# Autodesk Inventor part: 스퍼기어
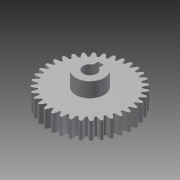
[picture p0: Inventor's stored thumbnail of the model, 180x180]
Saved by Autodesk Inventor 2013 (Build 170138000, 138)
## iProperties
Created: 2013-08
Part Number: 스퍼기어
Material: 강
Document SubType Name: Modeling
Designer: 한국산업디자인학원
Categories: <?xml version="1.0" encoding="UTF-16"?> <MemberInstance><Categories><FamilyTemplate><FamilyTemplateParameter ValueType="xs:double" Id="1" ObjectReferenceKey="da
Density: 1 g/cm^3
CustomPartVersion: 1
Author: 한국산업디자인학원
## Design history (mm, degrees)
sketch "Sketch1"
  geometry: C1 r 37 at (0, 0)
  constraints: 1 centre point
  dimensions: "d0" = 74 diameter of C1 (= da_da)
extrude "Extrusion1" new body sketch "Sketch1" distance "d1" = 15 (= da_b); taper "d2" = 0 deg
workplane "Work Plane2"
feature "피치 지름" dims "d4" = 10, "d5" = 0
workplane "Work Plane8"
workplane "Work Plane9"
feature "스퍼 기어" dims "da_b" = 15, "da_d" = 70, "da_aw" = 70, "da_da" = 74, "da_df" = 65, "da_dw" = 70, angle "da_beta" = 0 deg, "da_lefttooth" = 0, "da_righttooth" = 0
sketch "스케치3"
  geometry: C1 r 12.5 at (0, 0); A1 r 37 centre (0, 0) between (-5.788, 36.544) and (-7.422, 36.248) reference
  constraints: 1 centre point, 1 coincident
  dimensions: "d49" = 25 diameter of C1
extrude "돌출2" join sketch "스케치3" distance "d51" = 13; taper "d52" = 0 deg
sketch "스케치4"
  geometry: C1 r 12.5 at (0, 0); A1 r 32.5 centre (0, 0) between (9.347, 31.127) and (7.941, 31.515) reference
  constraints: 1 centre point, 1 coincident
  dimensions: "d53" = 25 diameter of C1
extrude "돌출3" join sketch "스케치4" distance "d55" = 3; taper "d56" = 0 deg
sketch "스케치5"
  geometry: C1 r 12.5 at (0, 0) reference; 1 further point
  constraints: 1 coincident
hole "구멍1" sketch "스케치5" at (0, 0) diameter "d57" = 12; stored, may be unused: countersink angle "d61" = 90 deg, drill point angle "d63" = 0 deg; dims "d58" = 6, "d59" = 4, "d60" = 2, "d62" = 31
sketch "스케치6"
  geometry: L1 (-2.5, 9.8)-(2.5, 9.8); L2 (2.5, 9.8)-(2.5, 0); L3 (2.5, 0)-(-2.5, 0); L4 (-2.5, 0)-(-2.5, 9.8); C1 r 6 at (0, 0) reference; 1 further point
  constraints: 8 end point, 2 parallel, 1 coincident, 1 horizontal, 1 midpoint, 1 perpendicular
  dimensions: "d64" = 9.8 distance between parallel lines of L3 L1; "d66" = 5 distance of L1.start L1.end
extrude "돌출4" cut sketch "스케치6" distance "d67" = 31; taper "d68" = 0 deg
body "Solid1"
sketch "Sketch2"
  geometry: C1 r 37 at (0, 0) reference; C2 r 35 at (0, 0)
  constraints: 1 centre point, 1 coincident
  dimensions: "d3" = 70 diameter of C2 (= da_dw)
body "Srf1"
other parameters: "d17" = 0, "d34" = 0.8976 (computed from da_z), "d39" = 0, "d41" = 0, "d47" = 0, "d48" = 0
